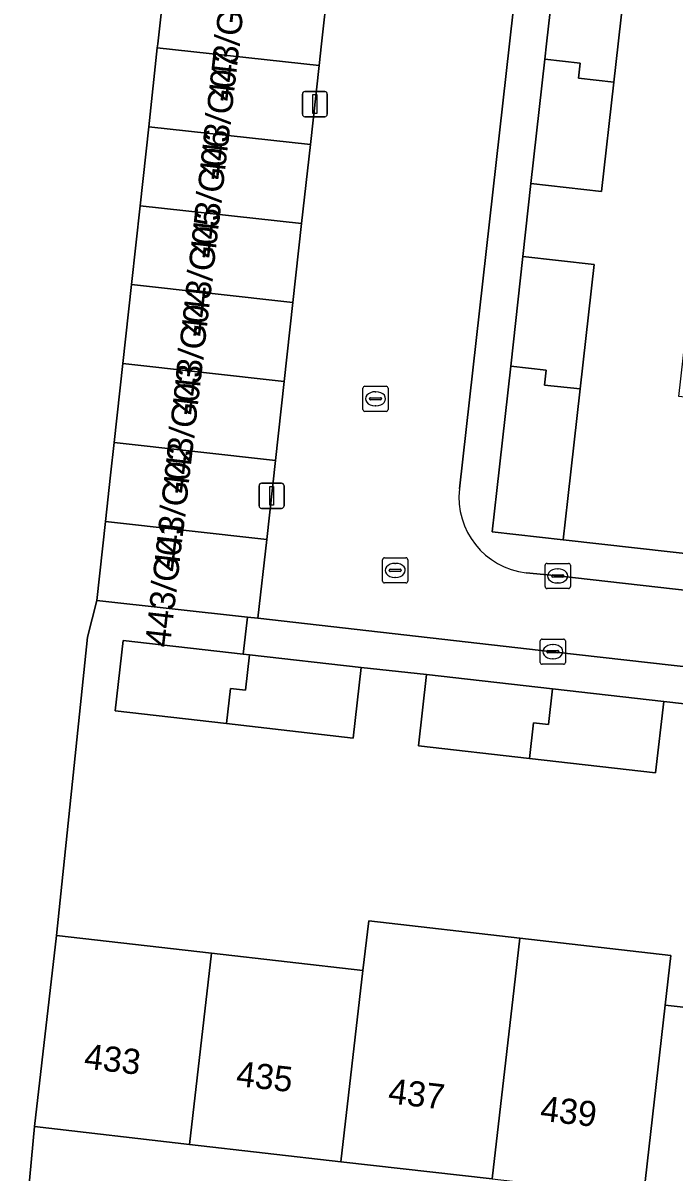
# Model space of a CAD drawing. Extents: x 161928 to 163071, y 386474 to 387428.
# Drawn here: x 162043.07 to 162068.97, y 386955.11 to 387000.83 of the extents above; entities that cross this region are included whole.
import ezdxf

# ---------------------------------------------------------------- set-up
doc = ezdxf.new("R2010")
doc.units = 0
for name, color, linetype in [('IMGEO_Erf', 7, 'Continuous'), ('IMGEO_Groenvoorziening', 7, 'Continuous'), ('IMGEO_Kolk', 7, 'Continuous'), ('IMGEO_Lichtmast', 7, 'Continuous'), ('IMGEO_Pand', 7, 'Continuous'), ('IMGEO_Pand_nummerreeks', 7, 'Continuous'), ('IMGEO_Rijbaan_lokaal_open', 7, 'Continuous'), ('IMGEO_Rioolput', 7, 'Continuous'), ('IMGEO_Voetpad_open', 7, 'Continuous')]:
    doc.layers.add(name, color=color, linetype=linetype)

msp = doc.modelspace()

# ---------------------------------------------------------------- linework, layer by layer
at = {"layer": 'IMGEO_Erf'}
for points in [[(162067.103, 387003.434), (162066.714, 387000), (162066.543, 386998.487), (162066.05, 386994.137), (162063.242, 386994.452), (162062.934, 386991.549), (162065.759, 386991.233), (162065.204, 386986.282), (162064.715, 386981.926), (162064.53, 386980.285), (162071.731, 386979.481), (162072.424, 386985.617), (162069.132, 386985.988), (162069.805, 386991.958), (162073.098, 386991.587), (162073.108, 386991.679), (162073.284, 386991.659), (162073.904, 386997.384), (162073.925, 386997.579), (162073.604, 386997.613), (162074.26, 387003.707)], [(162071.234, 386973.551), (162068.524, 386973.861), (162068.2, 386971.018), (162063.189, 386971.589), (162058.777, 386972.091), (162059.101, 386974.934), (162056.509, 386975.203), (162056.19, 386972.405), (162051.161, 386972.978), (162046.732, 386973.483), (162047.051, 386976.281), (162051.824, 386975.737), (162051.992, 386977.21), (162046.003, 386977.879), (162045.628, 386976.42), (162044.401, 386964.557), (162050.559, 386963.852), (162056.569, 386963.164), (162056.817, 386965.136), (162062.806, 386964.45), (162068.814, 386963.762), (162068.588, 386961.789), (162074.598, 386961.101)], [(162061.709, 386954.871), (162055.699, 386955.559), (162049.689, 386956.247), (162043.53, 386956.952), (162043.072, 386952.099)]]:
    msp.add_lwpolyline(points, dxfattribs=at)
at = {"layer": 'IMGEO_Groenvoorziening'}
msp.add_lwpolyline([(162043.072, 386952.099), (162043.53, 386956.952), (162044.401, 386964.557), (162045.628, 386976.42), (162046.003, 386977.879), (162046.346, 386981.011), (162046.547, 386982.85), (162046.689, 386984.151), (162047.033, 386987.291), (162047.377, 386990.431), (162047.721, 386993.57), (162048.065, 386996.71), (162048.408, 386999.85), (162048.425, 387000.002), (162048.756, 387002.989), (162049.103, 387006.128), (162049.45, 387009.268), (162049.798, 387012.407), (162050.145, 387015.546), (162050.501, 387018.763), (162050.667, 387020.399), (162051.69, 387030.446), (162052.105, 387034.212), (162052.938, 387041.772)], dxfattribs=at)
at = {"layer": 'IMGEO_Kolk'}
for p, q in [((162056.576, 386985.467), (162056.576, 386986.319)), ((162056.651, 386986.393), (162057.503, 386986.393)), ((162057.577, 386986.319), (162057.577, 386985.467)), ((162056.835, 386985.887), (162056.835, 386985.899)), ((162057.273, 386985.85), (162056.875, 386985.85)), ((162056.878, 386985.936), (162057.276, 386985.936)), ((162057.064, 386986.173), (162057.089, 386986.173)), ((162057.319, 386985.899), (162057.319, 386985.887)), ((162057.503, 386985.393), (162056.651, 386985.393)), ((162057.087, 386985.613), (162057.062, 386985.613)), ((162063.815, 386978.423), (162063.815, 386979.275)), ((162063.89, 386979.349), (162064.742, 386979.349)), ((162064.303, 386979.129), (162064.328, 386979.129)), ((162064.816, 386979.275), (162064.816, 386978.423)), ((162064.074, 386978.843), (162064.074, 386978.855)), ((162064.512, 386978.806), (162064.114, 386978.806)), ((162064.117, 386978.892), (162064.515, 386978.892)), ((162064.326, 386978.569), (162064.301, 386978.569)), ((162064.558, 386978.855), (162064.558, 386978.843)), ((162064.742, 386978.349), (162063.89, 386978.349)), ((162063.621, 386975.411), (162063.621, 386976.263)), ((162063.696, 386976.337), (162064.548, 386976.337)), ((162064.622, 386976.263), (162064.622, 386975.411)), ((162063.88, 386975.831), (162063.88, 386975.843)), ((162064.318, 386975.794), (162063.92, 386975.794)), ((162063.923, 386975.88), (162064.321, 386975.88)), ((162064.109, 386976.117), (162064.134, 386976.117)), ((162064.364, 386975.843), (162064.364, 386975.831)), ((162064.548, 386975.337), (162063.696, 386975.337)), ((162064.132, 386975.557), (162064.107, 386975.557))]:
    msp.add_line(p, q, dxfattribs=at)
for points in [[(162056.576, 386985.467), (162056.576, 386986.319)], [(162056.651, 386986.393), (162057.503, 386986.393)], [(162057.577, 386986.319), (162057.577, 386985.467)], [(162057.503, 386985.393), (162056.651, 386985.393)], [(162063.815, 386978.423), (162063.815, 386979.275)], [(162063.89, 386979.349), (162064.742, 386979.349)], [(162064.816, 386979.275), (162064.816, 386978.423)], [(162064.742, 386978.349), (162063.89, 386978.349)], [(162063.621, 386975.411), (162063.621, 386976.263)], [(162063.696, 386976.337), (162064.548, 386976.337)], [(162064.622, 386976.263), (162064.622, 386975.411)], [(162064.548, 386975.337), (162063.696, 386975.337)]]:
    msp.add_lwpolyline(points, dxfattribs=at)
for centre, radius, start, end in [((162056.653, 386986.317), 0.0765, 91.552, 178.448), ((162056.653, 386986.317), 0.0765, 91.552, 178.448), ((162057.501, 386986.317), 0.0765, 1.552, 88.448), ((162057.501, 386986.317), 0.0765, 1.552, 88.448), ((162056.875, 386985.896), 0.0403, 85.8775, 175.7526), ((162056.872, 386985.886), 0.0366, 178.938, 274.7102), ((162057.276, 386985.893), 0.043, 264.8664, 352.4533), ((162057.28, 386985.898), 0.0386, 1.7309, 96.639), ((162056.653, 386985.469), 0.0765, 181.552, 268.448), ((162056.653, 386985.469), 0.0765, 181.552, 268.448), ((162057.501, 386985.469), 0.0765, 271.552, 358.448), ((162057.501, 386985.469), 0.0765, 271.552, 358.448), ((162063.892, 386979.273), 0.0765, 91.552, 178.448), ((162063.892, 386979.273), 0.0765, 91.552, 178.448), ((162064.74, 386979.273), 0.0765, 1.552, 88.448), ((162064.74, 386979.273), 0.0765, 1.552, 88.448), ((162064.114, 386978.852), 0.0403, 85.8775, 175.7526), ((162064.111, 386978.842), 0.0366, 178.938, 274.7102), ((162064.515, 386978.849), 0.043, 264.8664, 352.4533), ((162064.519, 386978.854), 0.0386, 1.7309, 96.639), ((162063.892, 386978.425), 0.0765, 181.552, 268.448), ((162063.892, 386978.425), 0.0765, 181.552, 268.448), ((162064.74, 386978.425), 0.0765, 271.552, 358.448), ((162064.74, 386978.425), 0.0765, 271.552, 358.448), ((162063.698, 386976.261), 0.0765, 91.552, 178.448), ((162063.698, 386976.261), 0.0765, 91.552, 178.448), ((162064.546, 386976.261), 0.0765, 1.552, 88.448), ((162064.546, 386976.261), 0.0765, 1.552, 88.448), ((162063.92, 386975.84), 0.0403, 85.8775, 175.7526), ((162063.917, 386975.83), 0.0366, 178.938, 274.7102), ((162064.321, 386975.837), 0.043, 264.8664, 352.4533), ((162064.325, 386975.842), 0.0386, 1.7309, 96.639), ((162063.698, 386975.413), 0.0765, 181.552, 268.448), ((162063.698, 386975.413), 0.0765, 181.552, 268.448), ((162064.546, 386975.413), 0.0765, 271.552, 358.448), ((162064.546, 386975.413), 0.0765, 271.552, 358.448)]:
    msp.add_arc(centre, radius, start, end, dxfattribs=at)
for centre, major_axis, ratio, start_param, end_param in [((162057.063, 386985.893), (-0.387, 0.002), 0.722429, 4.712389, 7.853982), ((162057.088, 386985.893), (-0.39, 0.002), 0.717154, 1.570796, 4.712389), ((162064.302, 386978.849), (-0.387, 0.002), 0.722429, 4.712389, 7.853982), ((162064.327, 386978.849), (-0.39, 0.002), 0.717154, 1.570796, 4.712389), ((162064.108, 386975.837), (-0.387, 0.002), 0.722429, 4.712389, 7.853982), ((162064.133, 386975.837), (-0.39, 0.002), 0.717154, 1.570796, 4.712389)]:
    msp.add_ellipse(centre, major_axis=major_axis, ratio=ratio, start_param=start_param, end_param=end_param, dxfattribs=at)
at = {"layer": 'IMGEO_Lichtmast'}
for p, q in [((162054.171, 386997.21), (162054.171, 386998.01)), ((162054.171, 386998.01), (162054.171, 386997.21)), ((162054.271, 386998.11), (162055.061, 386998.11)), ((162055.061, 386998.11), (162054.271, 386998.11)), ((162055.161, 386998.01), (162055.161, 386997.21)), ((162055.161, 386997.21), (162055.161, 386998.01)), ((162055.061, 386997.11), (162054.271, 386997.11)), ((162054.271, 386997.11), (162055.061, 386997.11)), ((162052.451, 386981.635), (162052.451, 386982.435)), ((162052.451, 386982.435), (162052.451, 386981.635)), ((162052.551, 386982.535), (162053.341, 386982.535)), ((162053.341, 386982.535), (162052.551, 386982.535)), ((162053.441, 386982.435), (162053.441, 386981.635)), ((162053.441, 386981.635), (162053.441, 386982.435)), ((162053.341, 386981.535), (162052.551, 386981.535)), ((162052.551, 386981.535), (162053.341, 386981.535))]:
    msp.add_line(p, q, dxfattribs=at)
for points in [[(162054.591, 386997.985), (162054.741, 386997.985), (162054.741, 386997.235), (162054.591, 386997.235), (162054.591, 386997.985)], [(162052.871, 386982.41), (162053.021, 386982.41), (162053.021, 386981.66), (162052.871, 386981.66), (162052.871, 386982.41)]]:
    msp.add_lwpolyline(points, dxfattribs=at)
for centre, start, end in [((162054.271, 386998.01), 90, 180), ((162054.271, 386998.01), 90, 180), ((162055.061, 386998.01), 0, 90), ((162055.061, 386998.01), 360, 90), ((162054.271, 386997.21), 180, 270), ((162054.271, 386997.21), 180, 270), ((162055.061, 386997.21), 270, 0), ((162055.061, 386997.21), 270, 0), ((162052.551, 386982.435), 90, 180), ((162052.551, 386982.435), 90, 180), ((162053.341, 386982.435), 0, 90), ((162053.341, 386982.435), 360, 90), ((162052.551, 386981.635), 180, 270), ((162052.551, 386981.635), 180, 270), ((162053.341, 386981.635), 270, 0), ((162053.341, 386981.635), 270, 0)]:
    msp.add_arc(centre, 0.1, start, end, dxfattribs=at)
at = {"layer": 'IMGEO_Pand'}
for points in [[(162063.865, 387000), (162063.798, 386999.403), (162065.204, 386999.244), (162065.136, 386998.647), (162066.543, 386998.487), (162066.714, 387000), (162067.103, 387003.434), (162064.289, 387003.758)], [(162055.182, 387002.279), (162048.756, 387002.989), (162048.425, 387000.002), (162048.408, 386999.85), (162054.835, 386999.14), (162054.93, 387000)], [(162054.835, 386999.14), (162048.408, 386999.85), (162048.065, 386996.71), (162054.488, 386996)], [(162063.242, 386994.452), (162066.05, 386994.137), (162066.543, 386998.487), (162065.136, 386998.647), (162065.204, 386999.244), (162063.798, 386999.403)], [(162047.721, 386993.57), (162054.141, 386992.861), (162054.488, 386996), (162048.065, 386996.71)], [(162047.377, 386990.431), (162053.794, 386989.722), (162054.141, 386992.861), (162047.721, 386993.57)], [(162062.446, 386987.196), (162063.859, 386987.037), (162063.792, 386986.44), (162065.204, 386986.282), (162065.759, 386991.233), (162062.934, 386991.549)], [(162047.033, 386987.291), (162053.448, 386986.582), (162053.794, 386989.722), (162047.377, 386990.431)], [(162046.689, 386984.151), (162053.101, 386983.443), (162053.448, 386986.582), (162047.033, 386987.291)], [(162061.705, 386980.602), (162064.53, 386980.285), (162064.715, 386981.926), (162065.204, 386986.282), (162063.792, 386986.44), (162063.859, 386987.037), (162062.446, 386987.196), (162061.891, 386982.243)], [(162046.547, 386982.85), (162046.346, 386981.011), (162052.754, 386980.303), (162053.101, 386983.443), (162046.689, 386984.151)], [(162052.754, 386980.303), (162046.346, 386981.011), (162046.003, 386977.879), (162051.992, 386977.21), (162052.407, 386977.164)], [(162052.076, 386975.708), (162051.824, 386975.737), (162047.051, 386976.281), (162046.732, 386973.483), (162051.161, 386972.978), (162051.32, 386974.379), (162051.917, 386974.311)], [(162052.076, 386975.708), (162051.917, 386974.311), (162051.32, 386974.379), (162051.161, 386972.978), (162056.19, 386972.405), (162056.509, 386975.203)], [(162059.101, 386974.934), (162058.777, 386972.091), (162063.189, 386971.589), (162063.351, 386973.009), (162063.948, 386972.941), (162064.11, 386974.364)], [(162064.11, 386974.364), (162063.948, 386972.941), (162063.351, 386973.009), (162063.189, 386971.589), (162068.2, 386971.018), (162068.524, 386973.861)], [(162062.806, 386964.45), (162056.817, 386965.136), (162056.569, 386963.164), (162055.699, 386955.559), (162061.709, 386954.871), (162062.58, 386962.476)], [(162043.53, 386956.952), (162049.689, 386956.247), (162050.559, 386963.852), (162044.401, 386964.557)], [(162068.588, 386961.789), (162068.814, 386963.762), (162062.806, 386964.45), (162062.58, 386962.476), (162061.709, 386954.871), (162067.717, 386954.184)], [(162056.569, 386963.164), (162050.559, 386963.852), (162049.689, 386956.247), (162055.699, 386955.559)], [(162074.598, 386961.101), (162068.588, 386961.789), (162067.717, 386954.184), (162073.727, 386953.496)]]:
    msp.add_lwpolyline(points, close=True, dxfattribs=at)
at = {"layer": 'IMGEO_Rijbaan_lokaal_open'}
for points in [[(162062.393, 387000), (162064.316, 387017.15), (162056.916, 387017.976), (162056.569, 387014.837), (162056.222, 387011.697), (162055.875, 387008.558), (162055.529, 387005.418), (162055.182, 387002.279), (162054.93, 387000), (162054.835, 386999.14), (162054.488, 386996), (162054.141, 386992.861), (162053.794, 386989.722), (162053.448, 386986.582), (162053.101, 386983.443), (162052.754, 386980.303), (162052.407, 386977.164), (162064.122, 386975.837), (162082.461, 386973.766), (162084.103, 386973.567), (162084.434, 386976.577), (162082.773, 386976.758), (162064.316, 386978.849), (162063.064, 386978.976)], [(162060.41, 386982.313), (162062.393, 387000)]]:
    msp.add_lwpolyline(points, dxfattribs=at)
msp.add_arc((162063.414, 386981.978), 3.022, 173.6339, 263.3584, dxfattribs=at)
at = {"layer": 'IMGEO_Rioolput'}
for p, q in [((162057.358, 386978.644), (162057.358, 386979.496)), ((162057.433, 386979.57), (162058.285, 386979.57)), ((162058.359, 386979.496), (162058.359, 386978.644)), ((162057.617, 386979.064), (162057.617, 386979.076)), ((162058.055, 386979.027), (162057.657, 386979.027)), ((162057.66, 386979.113), (162058.058, 386979.113)), ((162057.846, 386979.35), (162057.871, 386979.35)), ((162058.101, 386979.076), (162058.101, 386979.064)), ((162058.285, 386978.57), (162057.433, 386978.57)), ((162057.869, 386978.79), (162057.844, 386978.79))]:
    msp.add_line(p, q, dxfattribs=at)
for points in [[(162057.358, 386978.644), (162057.358, 386979.496)], [(162057.433, 386979.57), (162058.285, 386979.57)], [(162058.359, 386979.496), (162058.359, 386978.644)], [(162058.285, 386978.57), (162057.433, 386978.57)]]:
    msp.add_lwpolyline(points, dxfattribs=at)
for centre, radius, start, end in [((162057.435, 386979.494), 0.0765, 91.552, 178.448), ((162057.435, 386979.494), 0.0765, 91.552, 178.448), ((162058.283, 386979.494), 0.0765, 1.552, 88.448), ((162058.283, 386979.494), 0.0765, 1.552, 88.448), ((162057.657, 386979.073), 0.0403, 85.8775, 175.7526), ((162057.654, 386979.063), 0.0366, 178.938, 274.7102), ((162058.058, 386979.07), 0.043, 264.8664, 352.4533), ((162058.062, 386979.075), 0.0386, 1.7309, 96.639), ((162057.435, 386978.646), 0.0765, 181.552, 268.448), ((162057.435, 386978.646), 0.0765, 181.552, 268.448), ((162058.283, 386978.646), 0.0765, 271.552, 358.448), ((162058.283, 386978.646), 0.0765, 271.552, 358.448)]:
    msp.add_arc(centre, radius, start, end, dxfattribs=at)
for centre, major_axis, ratio, start_param, end_param in [((162057.845, 386979.07), (-0.387, 0.002), 0.722429, 4.712389, 7.853982), ((162057.87, 386979.07), (-0.39, 0.002), 0.717154, 1.570796, 4.712389)]:
    msp.add_ellipse(centre, major_axis=major_axis, ratio=ratio, start_param=start_param, end_param=end_param, dxfattribs=at)
at = {"layer": 'IMGEO_Voetpad_open'}
for points in [[(162064.316, 387017.15), (162062.393, 387000), (162060.41, 386982.313)], [(162071.731, 386979.481), (162064.53, 386980.285), (162061.705, 386980.602), (162061.891, 386982.243), (162062.446, 386987.196), (162062.934, 386991.549), (162063.242, 386994.452), (162063.798, 386999.403), (162063.865, 387000), (162064.289, 387003.758)], [(162063.064, 386978.976), (162064.316, 386978.849), (162082.773, 386976.758), (162084.434, 386976.577), (162085.474, 386976.471), (162085.531, 386977.917), (162081.569, 386978.371), (162071.731, 386979.481)]]:
    msp.add_lwpolyline(points, dxfattribs=at)
msp.add_lwpolyline([(162064.122, 386975.837), (162052.407, 386977.164), (162051.992, 386977.21), (162051.824, 386975.737), (162052.076, 386975.708), (162056.509, 386975.203), (162059.101, 386974.934), (162064.11, 386974.364), (162068.524, 386973.861), (162071.234, 386973.551), (162076.207, 386972.983), (162081.848, 386972.339), (162084.831, 386972.042), (162085.131, 386973.429), (162084.103, 386973.567), (162082.461, 386973.766)], close=True, dxfattribs=at)
msp.add_arc((162063.414, 386981.978), 3.022, 173.6339, 263.3584, dxfattribs=at)

# ---------------------------------------------------------------- texts
at = {"layer": 'IMGEO_Pand_nummerreeks'}
for s, rotation, p in [('443/G08', 83.4013, (162051.415, 386997.691)), ('443/G07', 83.4013, (162051.054, 386994.571)), ('443/G06', 83.4013, (162050.693, 386991.454)), ('443/G05', 83.4013, (162050.333, 386988.337)), ('443/G04', 83.4013, (162049.972, 386985.22)), ('443/G03', 83.4013, (162049.611, 386982.103)), ('443/G02', 83.4013, (162049.25, 386978.98)), ('443/G01', 83.3997, (162048.903, 386975.978)), ('433', 353.4691, (162045.468, 386959.266)), ('435', 353.4691, (162051.507, 386958.575)), ('437', 353.4691, (162057.546, 386957.884)), ('439', 353.4683, (162063.585, 386957.192))]:
    msp.add_text(s, height=1, rotation=rotation, dxfattribs=at).set_placement(p)

doc.saveas('drawing.dxf')
